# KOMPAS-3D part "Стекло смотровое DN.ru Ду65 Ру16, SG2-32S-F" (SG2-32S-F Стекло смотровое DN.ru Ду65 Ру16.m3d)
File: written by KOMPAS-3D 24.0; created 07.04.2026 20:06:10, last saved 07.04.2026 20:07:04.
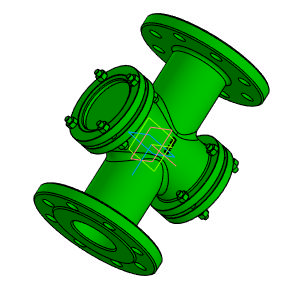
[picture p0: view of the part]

Document properties: Автор: Main; Полное имя файла: D:\DN.ru Аутсерс\Стекло смотровое DN.ru\SG2-32S-F Стекло смотровое DN.ru Ду65 Ру16\SG2-32S-F Стекло смотровое DN.ru Ду65 Ру16.m3d

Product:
- Body: Тело 1  | qty 1
    Масса: 13.01185
- Part/product: Стекло смотровое DN.ru Ду65 Ру16  | designation SG2-32S-F
    Масса: 14
    Раздел спецификации: Прочие изделия
    Примечание: D500-00109

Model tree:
1. Операция без истории:1

Expressions: SG2-32S-F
